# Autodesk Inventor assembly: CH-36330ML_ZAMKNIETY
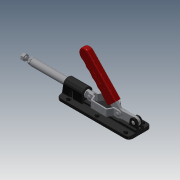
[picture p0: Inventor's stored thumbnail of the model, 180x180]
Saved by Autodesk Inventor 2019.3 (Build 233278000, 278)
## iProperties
Created: 2012-06
Part Number: CH-36330ML_ZAMKNIETY
Material: Ogólny
Document SubType Name: Assembly
Designer: CADENGINEERING4
Sending System: PRO/ENGINEER BY PARAMETRIC TECHNOLOGY CORPORATION, 2007170
Preprocessor: PRO/ENGINEER BY PARAMETRIC TECHNOLOGY CORPORATION, 2007170
Title: CH-36330MLASM0001_ASM
Author: Administrator
Revision Number: 2LAST_VERSION
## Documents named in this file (11)
- D:\Vault_2016\Projekty\STRONA\Push-pull clamp\CH-36330ML\CH-36330ML_ZAMKNIETY.iam
- D:\Vault_2016\Projekty\STRONA\Push-pull clamp\CH-36330ML\36330MLDC.ipt
- D:\Vault_2016\Projekty\STRONA\Push-pull clamp\CH-36330ML\36330-MLSHOUBA.ipt
- D:\Vault_2016\Projekty\STRONA\Push-pull clamp\CH-36330ML\36330MLSHOUB.ipt
- D:\Vault_2016\Projekty\STRONA\Push-pull clamp\CH-36330ML\36330-MLDINGZHOU.ipt
- D:\Vault_2016\Projekty\STRONA\Push-pull clamp\CH-36330ML\36330-MLLIANGA.ipt
- D:\Vault_2016\Projekty\STRONA\Push-pull clamp\CH-36330ML\PRT0001.ipt
- D:\Vault_2016\Projekty\STRONA\Push-pull clamp\CH-36330ML\M8_NUT_____.ipt
- D:\Vault_2016\Projekty\STRONA\Push-pull clamp\CH-36330ML\CH-SA-085012_SPINDLE_SUPPLIED__.ipt
- D:\Vault_2016\Projekty\STRONA\Push-pull clamp\CH-36330ML\PRT0002.ipt
- D:\Vault_2016\Projekty\STRONA\Push-pull clamp\CH-36330ML\PRT0003.ipt
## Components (11 placed, 11 different names)
1. 36330MLDC_0
2. 36330-MLSHOUBA_1
3. 36330MLSHOUB_2
4. 36330-MLDINGZHOU_3
5. 36330-MLLIANGA_4
6. PRT0001_5
7. M8_NUT______6
8. CH-SA-085012_SPINDLE_SUPPLIED___7
9. PRT0002_8
10. PRT0002_9
11. PRT0003_10
